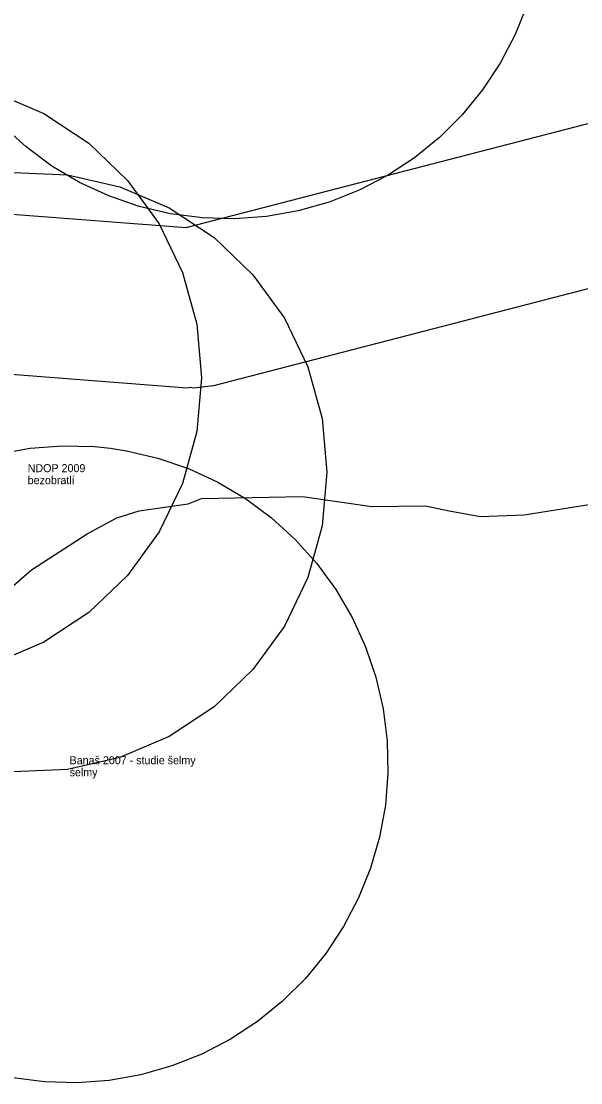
# Model space of a CAD drawing. Extents: x -477403 to -465463, y -1159182 to -1149227.
# Drawn here: x -475193.1 to -475053.2, y -1150742.2 to -1150476.9 of the extents above; entities that cross this region are included whole.
import ezdxf

# ---------------------------------------------------------------- set-up
doc = ezdxf.new("R2010")
doc.units = 0
for name, color, linetype in [('Vrstva 1', 7, 'Continuous'), ('Vrstva 10_stav', 7, 'Continuous'), ('Vrstva 2', 7, 'Continuous')]:
    doc.layers.add(name, color=color, linetype=linetype)

msp = doc.modelspace()

# ---------------------------------------------------------------- linework, layer by layer
at = {"layer": 'Vrstva 10_stav'}
for points in [[(-474589.739, -1150400.278), (-474897.823, -1150503.932), (-474898.123, -1150503.981), (-474899.19, -1150504.339), (-475145.021, -1150567.966), (-475150.033, -1150568.604), (-475150.879, -1150568.435), (-475151.567, -1150568.545), (-475226.762, -1150562.76), (-475232.882, -1150561.297), (-475239.37, -1150556.961), (-475243.706, -1150550.473), (-475245.228, -1150542.819), (-475243.706, -1150535.166), (-475239.37, -1150528.677), (-475232.882, -1150524.342), (-475223.694, -1150522.878), (-475151.82, -1150528.407), (-474909.903, -1150465.793), (-474601.12, -1150361.904)], [(-475066.55, -1150472.741), (-475069.55, -1150480.2), (-475073.29, -1150487.316), (-475077.73, -1150494.018), (-475082.826, -1150500.236), (-475088.525, -1150505.907), (-475094.768, -1150510.972), (-475101.491, -1150515.38), (-475108.626, -1150519.085), (-475116.099, -1150522.049), (-475123.834, -1150524.242), (-475131.751, -1150525.641), (-475139.769, -1150526.231), (-475147.805, -1150526.008), (-475155.777, -1150524.973), (-475163.604, -1150523.137), (-475171.205, -1150520.518), (-475178.502, -1150517.143), (-475185.421, -1150513.048), (-475191.889, -1150508.274), (-475197.841, -1150502.87)], [(-475199.824, -1150494.671), (-475187.46, -1150499.955), (-475176.238, -1150507.363), (-475166.52, -1150516.655), (-475158.616, -1150527.533), (-475152.782, -1150539.647), (-475149.205, -1150552.608), (-475148, -1150566), (-475149.205, -1150579.392), (-475152.782, -1150592.353), (-475158.616, -1150604.467), (-475166.52, -1150615.345), (-475176.238, -1150624.637), (-475187.46, -1150632.045), (-475199.824, -1150637.329)], [(-475195.005, -1150514.636), (-475181.573, -1150515.239), (-475168.464, -1150518.231), (-475156.1, -1150523.515), (-475144.878, -1150530.923), (-475135.16, -1150540.215), (-475127.256, -1150551.093), (-475121.422, -1150563.207), (-475117.845, -1150576.168), (-475116.64, -1150589.56), (-475117.845, -1150602.952), (-475121.422, -1150615.913), (-475127.256, -1150628.027), (-475135.16, -1150638.905), (-475144.878, -1150648.197), (-475156.1, -1150655.605), (-475168.464, -1150660.889), (-475181.573, -1150663.881), (-475195.005, -1150664.484)], [(-475198.819, -1150584.94), (-475190.876, -1150583.536), (-475182.831, -1150582.943), (-475174.767, -1150583.167), (-475170.754, -1150583.585), (-475166.768, -1150584.206), (-475158.914, -1150586.049), (-475151.288, -1150588.676), (-475143.966, -1150592.062), (-475137.024, -1150596.171), (-475130.534, -1150600.962), (-475124.562, -1150606.384), (-475119.169, -1150612.383), (-475114.41, -1150618.896), (-475110.335, -1150625.858), (-475106.985, -1150633.196), (-475104.394, -1150640.836), (-475102.59, -1150648.698), (-475101.591, -1150656.703), (-475101.406, -1150664.767), (-475102.038, -1150672.809), (-475103.481, -1150680.746), (-475105.719, -1150688.496), (-475108.729, -1150695.979), (-475112.482, -1150703.12), (-475116.937, -1150709.845), (-475122.05, -1150716.084), (-475127.768, -1150721.774), (-475134.032, -1150726.857), (-475140.778, -1150731.279), (-475147.937, -1150734.997), (-475155.436, -1150737.971), (-475163.197, -1150740.171), (-475171.14, -1150741.574), (-475179.185, -1150742.167), (-475187.249, -1150741.943), (-475195.248, -1150740.905)], [(-475210.625, -1150631.375), (-475190.5, -1150614), (-475176.594, -1150605), (-475169.219, -1150601), (-475163.625, -1150599.25), (-475151.344, -1150597.5), (-475148.031, -1150596.125), (-475122.75, -1150595.625), (-475105.438, -1150598.125), (-475092.031, -1150598), (-475086.062, -1150599.25), (-475078.219, -1150600.625), (-475067.344, -1150600.25), (-475049.531, -1150597.375)]]:
    msp.add_lwpolyline(points, dxfattribs=at)

# ---------------------------------------------------------------- texts
at = {"layer": 'Vrstva 1'}
for s, p in [('bezobratlí', (-475191.489, -1150592.56)), ('bezobratlí', (-475191.489, -1150592.56)), ('šelmy', (-475181.008, -1150665.555)), ('šelmy', (-475181.008, -1150665.555))]:
    msp.add_text(s, height=2, dxfattribs=at).set_placement(p)
at = {"layer": 'Vrstva 2'}
for s, p in [('NDOP 2009', (-475191.489, -1150589.56)), ('NDOP 2009', (-475191.489, -1150589.56)), ('Banaš 2007 - studie šelmy', (-475181.008, -1150662.555)), ('Banaš 2007 - studie šelmy', (-475181.008, -1150662.555))]:
    msp.add_text(s, height=2, dxfattribs=at).set_placement(p)

doc.saveas('drawing.dxf')
